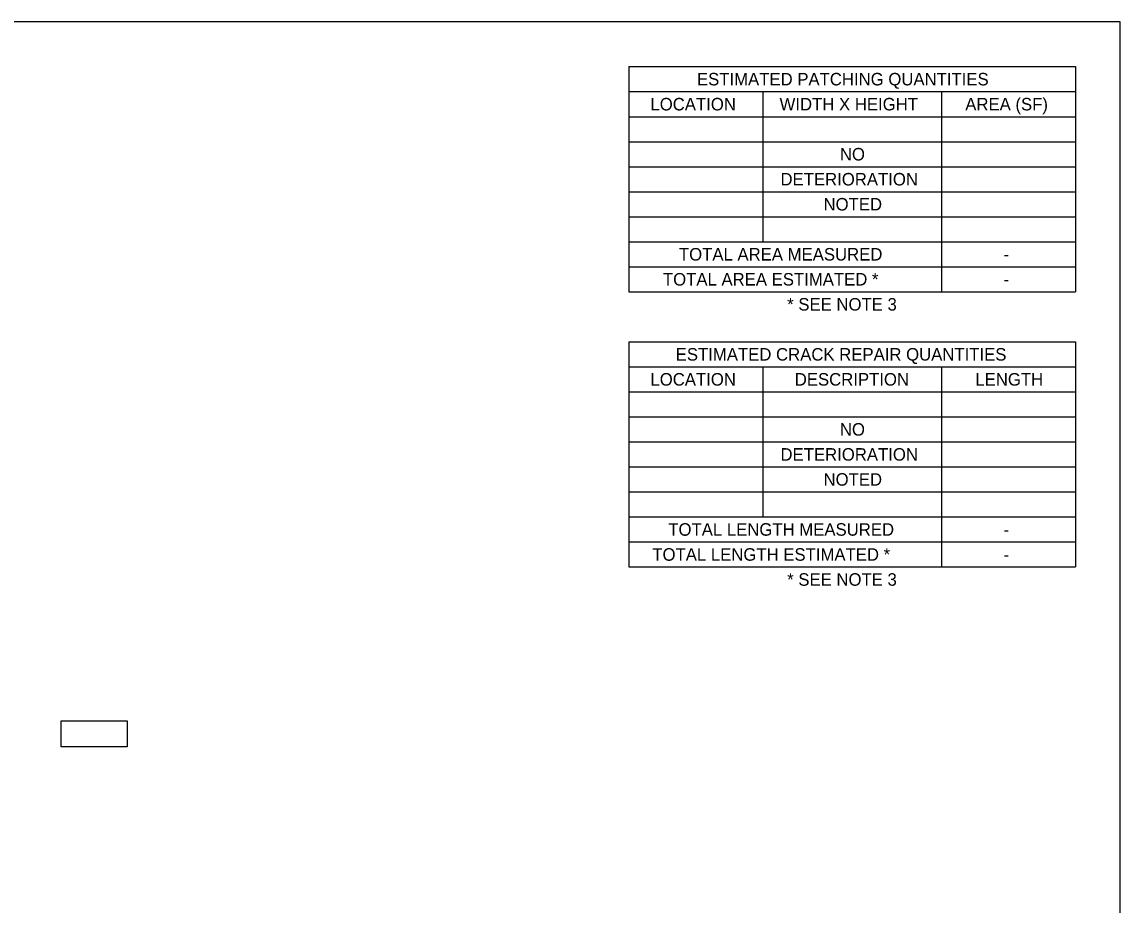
# Model space of a CAD drawing. Extents: x 100 to 130.5, y 100 to 121.
# Drawn here: x 118.21 to 130.5, y 111.12 to 121 of the extents above; entities that cross this region are included whole.
import ezdxf

# ---------------------------------------------------------------- set-up
doc = ezdxf.new("R2010")
doc.units = 0
for name, color, linetype in [('BR_P_Gen_Text', 7, 'Continuous'), ('SC_Scratch1', 7, 'Continuous'), ('SH_Masking', 7, 'Continuous')]:
    doc.layers.add(name, color=color, linetype=linetype)

msp = doc.modelspace()

# ---------------------------------------------------------------- linework, layer by layer
at = {"layer": 'BR_P_Gen_Text'}
for p, q in [((125, 120.5), (125, 117.98)), ((125, 120.5), (130, 120.5)), ((130, 120.5), (130, 117.98)), ((125, 120.22), (130, 120.22)), ((126.5, 120.22), (126.5, 118.54)), ((128.5, 120.22), (128.5, 117.98)), ((125, 119.94), (130, 119.94)), ((125, 119.66), (130, 119.66)), ((125, 119.38), (130, 119.38)), ((125, 119.1), (130, 119.1)), ((125, 118.82), (130, 118.82)), ((125, 118.54), (130, 118.54)), ((125, 118.26), (130, 118.26)), ((125, 117.98), (130, 117.98)), ((125, 117.42), (125, 114.9)), ((125, 117.42), (130, 117.42)), ((130, 117.42), (130, 114.9)), ((125, 117.14), (130, 117.14)), ((126.5, 117.14), (126.5, 115.46)), ((128.5, 117.14), (128.5, 114.9)), ((125, 116.86), (130, 116.86)), ((125, 116.58), (130, 116.58)), ((125, 116.3), (130, 116.3)), ((125, 116.02), (130, 116.02)), ((125, 115.74), (130, 115.74)), ((125, 115.46), (130, 115.46)), ((125, 115.18), (130, 115.18)), ((125, 114.9), (130, 114.9))]:
    msp.add_line(p, q, dxfattribs=at)
at = {"layer": 'SC_Scratch1'}
msp.add_lwpolyline([(100, 100), (130.5, 100), (130.5, 121), (100, 121)], close=True, dxfattribs=at)
at = {"layer": 'SH_Masking'}
msp.add_lwpolyline([(118.643, 113.178), (119.384, 113.178), (119.384, 112.887), (118.643, 112.887)], close=True, dxfattribs=at)

# ---------------------------------------------------------------- texts
at = {"layer": 'BR_P_Gen_Text'}
for s, p in [('ESTIMATED PATCHING QUANTITIES', (125.763, 120.29)), ('LOCATION', (125.242, 120.01)), ('WIDTH X HEIGHT', (126.688, 120.01)), ('AREA (SF)', (128.767, 120.01)), ('NO', (127.363, 119.45)), ('DETERIORATION', (126.698, 119.17)), ('NOTED', (127.18, 118.89)), ('TOTAL AREA MEASURED', (125.561, 118.33)), ('-', (129.197, 118.33)), ('TOTAL AREA ESTIMATED *', (125.382, 118.05)), ('-', (129.197, 118.05)), ('* SEE NOTE 3', (126.773, 117.77)), ('ESTIMATED CRACK REPAIR QUANTITIES', (125.525, 117.21)), ('LOCATION', (125.242, 116.93)), ('DESCRIPTION', (126.858, 116.93)), ('LENGTH', (128.88, 116.93)), ('NO', (127.363, 116.37)), ('DETERIORATION', (126.698, 116.09)), ('NOTED', (127.18, 115.81)), ('TOTAL LENGTH MEASURED', (125.442, 115.25)), ('-', (129.197, 115.25)), ('TOTAL LENGTH ESTIMATED *', (125.263, 114.97)), ('-', (129.197, 114.97)), ('* SEE NOTE 3', (126.773, 114.69))]:
    msp.add_text(s, height=0.14, dxfattribs=at).set_placement(p)

doc.saveas('drawing.dxf')
